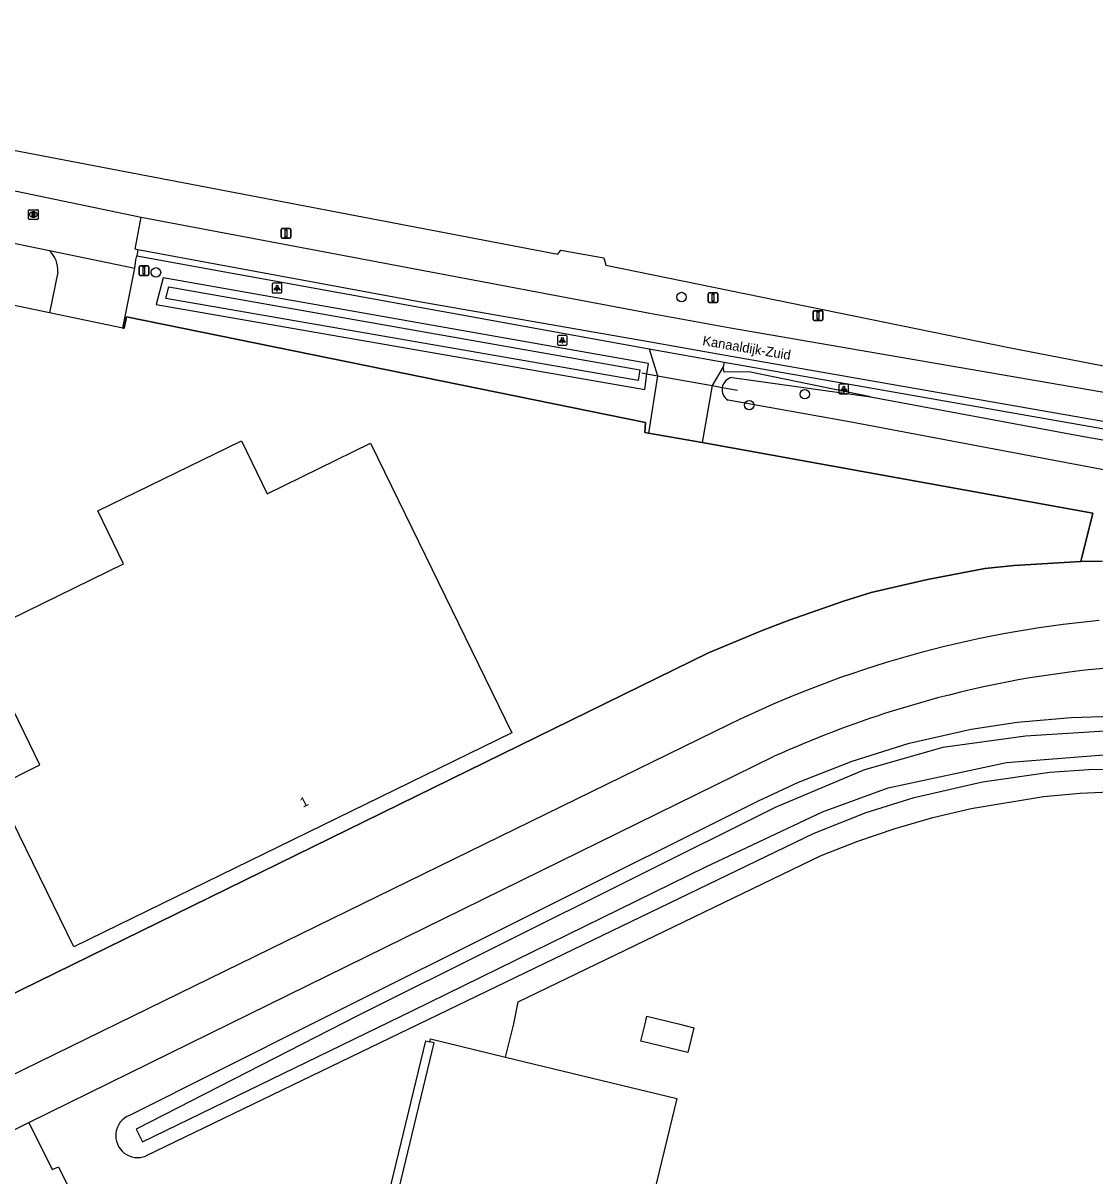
# Model space of a CAD drawing. Extents: x 163046 to 165074, y 382019 to 382874.
# Drawn here: x 163250 to 163360.8, y 382734.3 to 382853.5 of the extents above; entities that cross this region are included whole.
import ezdxf

# ---------------------------------------------------------------- set-up
doc = ezdxf.new("R2010")
doc.units = 0
for name, color, linetype in [('IMGEO_Afsluitpaal', 7, 'Continuous'), ('IMGEO_Boom', 7, 'Continuous'), ('IMGEO_Duiker', 7, 'Continuous'), ('IMGEO_Fietspad_gesloten', 7, 'Continuous'), ('IMGEO_Groenvoorziening', 7, 'Continuous'), ('IMGEO_Hek', 7, 'Continuous'), ('IMGEO_Lichtpunt', 7, 'Continuous'), ('IMGEO_Openbare_ruimte_label', 7, 'Continuous'), ('IMGEO_Pand', 7, 'Continuous'), ('IMGEO_Pand_nummerreeks', 7, 'Continuous'), ('IMGEO_Rijbaan_lokaal_gesloten', 7, 'Continuous'), ('IMGEO_Rijbaan_lokaal_halfverhard', 7, 'Continuous'), ('IMGEO_Rijbaan_lokaal_open', 7, 'Continuous'), ('IMGEO_Rioolput', 7, 'Continuous'), ('IMGEO_Verkeersbordpaal', 7, 'Continuous'), ('IMGEO_Voetpad_open', 7, 'Continuous'), ('IMGEO_Waterloop', 7, 'Continuous')]:
    doc.layers.add(name, color=color, linetype=linetype)

msp = doc.modelspace()

# ---------------------------------------------------------------- linework, layer by layer
at = {"layer": 'IMGEO_Afsluitpaal'}
for p, q in [((163320.83, 382824.69), (163320.83, 382825.49)), ((163320.83, 382825.49), (163320.83, 382824.69)), ((163320.93, 382825.59), (163321.72, 382825.59)), ((163321.72, 382825.59), (163320.93, 382825.59)), ((163321.82, 382825.49), (163321.82, 382824.69)), ((163321.82, 382824.69), (163321.82, 382825.49)), ((163321.72, 382824.59), (163320.93, 382824.59)), ((163320.93, 382824.59), (163321.72, 382824.59)), ((163331.68, 382822.85), (163331.68, 382823.65)), ((163331.68, 382823.65), (163331.68, 382822.85)), ((163331.78, 382823.75), (163332.57, 382823.75)), ((163332.57, 382823.75), (163331.78, 382823.75)), ((163332.67, 382823.65), (163332.67, 382822.85)), ((163332.67, 382822.85), (163332.67, 382823.65)), ((163332.57, 382822.75), (163331.78, 382822.75)), ((163331.78, 382822.75), (163332.57, 382822.75))]:
    msp.add_line(p, q, dxfattribs=at)
for points in [[(163321.25, 382825.47), (163321.4, 382825.47), (163321.4, 382824.72), (163321.25, 382824.72), (163321.25, 382825.47)], [(163332.1, 382823.62), (163332.25, 382823.62), (163332.25, 382822.87), (163332.1, 382822.87), (163332.1, 382823.62)]]:
    msp.add_lwpolyline(points, dxfattribs=at)
for centre, start, end in [((163320.93, 382825.49), 90, 180), ((163320.93, 382825.49), 90, 180), ((163321.72, 382825.49), 0, 90), ((163321.72, 382825.49), 360, 90), ((163320.93, 382824.69), 180, 270), ((163320.93, 382824.69), 180, 270), ((163321.72, 382824.69), 270, 0), ((163321.72, 382824.69), 270, 0), ((163331.78, 382823.65), 90, 180), ((163331.78, 382823.65), 90, 180), ((163332.57, 382823.65), 0, 90), ((163332.57, 382823.65), 360, 90), ((163331.78, 382822.85), 180, 270), ((163331.78, 382822.85), 180, 270), ((163332.57, 382822.85), 270, 0), ((163332.57, 382822.85), 270, 0)]:
    msp.add_arc(centre, 0.1, start, end, dxfattribs=at)
at = {"layer": 'IMGEO_Boom'}
for centre in [(163263.72, 382827.71), (163318.07, 382825.16), (163330.81, 382815.11), (163325.07, 382813.99)]:
    msp.add_circle(centre, 0.489, dxfattribs=at)
at = {"layer": 'IMGEO_Duiker'}
msp.add_lwpolyline([(163313.96, 382817.31), (163314.48, 382817.22), (163315.59, 382817.02), (163321.22, 382816), (163322.27, 382815.81), (163323.84, 382815.53)], dxfattribs=at)
at = {"layer": 'IMGEO_Fietspad_gesloten'}
msp.add_lwpolyline([(163262.2, 382833.43), (163314.79, 382823.48), (163323.12, 382821.97), (163364.34, 382814.88), (163364.32, 382814.73), (163391.13, 382810.02), (163404.12, 382807.82), (163422.79, 382804.65), (163452.38, 382800.08), (163452.39, 382800.23), (163481.75, 382795.75), (163600.16, 382778.49), (163659.31, 382769.79), (163694.75, 382764.5), (163718.27, 382760.99), (163718.28, 382761.09), (163777.46, 382752.55), (163894.24, 382735.48), (163935.71, 382729.35)], dxfattribs=at)
at = {"layer": 'IMGEO_Groenvoorziening'}
for points in [[(163252.7, 382823.52), (163242.43, 382825.65), (163242.33, 382825.25), (163240, 382825.68), (163241.32, 382832.3)], [(163264.46, 382827.14), (163263.75, 382824.38), (163314.26, 382815.6), (163314.48, 382817.22), (163314.64, 382818.3), (163264.46, 382827.14)], [(163314.65, 382811.1), (163314.26, 382811.17), (163314.35, 382812.18), (163260.67, 382823.11), (163260.43, 382821.93), (163260.28, 382821.96)], [(163337.61, 382814.84), (163325.03, 382817.42), (163322.49, 382817.39), (163322.36, 382817.94)], [(163359.37, 382797.83), (163360.61, 382802.83), (163320.19, 382810.11)], [(163200.21, 382729.51), (163222.08, 382740.26), (163242.58, 382750), (163320.84, 382788.38), (163326.4, 382790.68), (163329.21, 382791.76), (163334.82, 382793.72), (163337.67, 382794.6), (163343.5, 382795.94), (163349.43, 382797.09), (163352.45, 382797.4), (163359.37, 382797.83)], [(163359.37, 382797.83), (163374.85, 382798.03), (163401.89, 382794.15), (163410.94, 382792.85), (163500, 382779.47), (163535.41, 382774.6), (163550.62, 382772.33), (163693.06, 382751.36), (163828.8, 382731.36), (163846.1, 382728.88), (163873.33, 382724.84), (163916.5, 382718.52), (163943.51, 382714.37), (163981.6, 382708.67), (164080.42, 382694.02), (164103.91, 382690.52), (164197.42, 382676.27), (164217.65, 382673.07), (164282.56, 382663.33), (164518.36, 382627.93)], [(163410.61, 382775.99), (163377.55, 382781.04), (163372.54, 382781.55), (163367.86, 382781.78), (163363.62, 382781.82), (163358.36, 382781.66), (163352.77, 382781.17), (163348.02, 382780.45), (163341.46, 382778.95), (163335.66, 382777.14), (163330.14, 382774.97), (163325.99, 382773.04), (163279.88, 382750), (163260.97, 382740.55)], [(163290.93, 382750), (163331.78, 382769.74), (163337.15, 382771.86), (163342.11, 382773.43), (163349.17, 382775.05), (163356.16, 382776.02), (163360.19, 382776.32), (163367.6, 382776.42), (163374.36, 382776.08), (163380.14, 382775.41), (163410.26, 382770.79)], [(163299.86, 382746.58), (163300.71, 382750), (163301.17, 382752.29), (163332.52, 382767.41), (163336.3, 382768.91), (163340.15, 382770.21), (163344.05, 382771.34), (163348.01, 382772.28), (163355.5, 382773.52), (163359.28, 382773.88), (163363.07, 382774.05), (163367.27, 382774.02), (163371.45, 382773.73), (163379.79, 382772.82), (163396.27, 382770.52), (163405.32, 382768.66), (163412.39, 382767.2)], [(163262.68, 382736.35), (163290.93, 382750)], [(163250.57, 382739.8), (163252.99, 382734.96), (163253.66, 382735.24), (163267.35, 382707.42), (163272.62, 382706.27)]]:
    msp.add_lwpolyline(points, dxfattribs=at)
msp.add_arc((163261.83, 382738.45), 2.27, 112.1789, 292.2118, dxfattribs=at)
at = {"layer": 'IMGEO_Hek'}
for points in [[(163260.28, 382821.96), (163260.43, 382821.93), (163260.67, 382823.11), (163314.35, 382812.18), (163314.26, 382811.17), (163314.65, 382811.1)], [(163314.65, 382811.1), (163320.19, 382810.11)], [(163320.19, 382810.11), (163360.61, 382802.83), (163359.37, 382797.83)], [(163359.37, 382797.83), (163352.45, 382797.4), (163349.43, 382797.09), (163343.5, 382795.94), (163337.67, 382794.6), (163334.82, 382793.72), (163329.21, 382791.76), (163326.4, 382790.68), (163320.84, 382788.38), (163242.58, 382750), (163222.08, 382740.26)], [(163401.89, 382794.15), (163374.85, 382798.03), (163359.37, 382797.83)]]:
    msp.add_lwpolyline(points, dxfattribs=at)
at = {"layer": 'IMGEO_Lichtpunt'}
for p, q in [((163275.75, 382826.49), (163275.75, 382825.68)), ((163275.75, 382826.49), (163275.75, 382825.68)), ((163276.65, 382826.58), (163275.84, 382826.58)), ((163276.65, 382826.58), (163275.84, 382826.58)), ((163276.74, 382825.68), (163276.74, 382826.49)), ((163276.74, 382825.68), (163276.74, 382826.49)), ((163275.84, 382825.58), (163276.65, 382825.58)), ((163275.84, 382825.58), (163276.65, 382825.58)), ((163306.14, 382821.18), (163305.34, 382821.18)), ((163306.14, 382821.18), (163305.34, 382821.18)), ((163305.24, 382821.09), (163305.24, 382820.28)), ((163305.24, 382821.09), (163305.24, 382820.28)), ((163305.34, 382820.18), (163306.14, 382820.18)), ((163305.34, 382820.18), (163306.14, 382820.18)), ((163306.24, 382820.28), (163306.24, 382821.09)), ((163306.24, 382820.28), (163306.24, 382821.09)), ((163334.34, 382816.05), (163334.34, 382815.24)), ((163334.34, 382816.05), (163334.34, 382815.24)), ((163335.25, 382816.14), (163334.44, 382816.14)), ((163335.25, 382816.14), (163334.44, 382816.14)), ((163335.34, 382815.24), (163335.34, 382816.05)), ((163335.34, 382815.24), (163335.34, 382816.05)), ((163334.44, 382815.14), (163335.25, 382815.14)), ((163334.44, 382815.14), (163335.25, 382815.14))]:
    msp.add_line(p, q, dxfattribs=at)
for points in [[(163276.12, 382826.15), (163276.16, 382826.12), (163275.97, 382825.86), (163275.93, 382825.89), (163276.12, 382826.15)], [(163276.22, 382826.1), (163276.27, 382826.1), (163276.27, 382825.78), (163276.22, 382825.78), (163276.22, 382826.1)], [(163276.33, 382826.12), (163276.37, 382826.15), (163276.56, 382825.89), (163276.52, 382825.86), (163276.33, 382826.12)], [(163305.62, 382820.75), (163305.65, 382820.72), (163305.47, 382820.46), (163305.43, 382820.49), (163305.62, 382820.75)], [(163305.72, 382820.7), (163305.76, 382820.7), (163305.76, 382820.38), (163305.72, 382820.38), (163305.72, 382820.7)], [(163305.83, 382820.72), (163305.87, 382820.75), (163306.05, 382820.49), (163306.01, 382820.46), (163305.83, 382820.72)], [(163334.72, 382815.71), (163334.76, 382815.68), (163334.57, 382815.42), (163334.53, 382815.45), (163334.72, 382815.71)], [(163334.82, 382815.66), (163334.87, 382815.66), (163334.87, 382815.34), (163334.82, 382815.34), (163334.82, 382815.66)], [(163334.93, 382815.68), (163334.97, 382815.71), (163335.15, 382815.45), (163335.12, 382815.42), (163334.93, 382815.68)]]:
    msp.add_lwpolyline(points, dxfattribs=at)
for centre in [(163276.25, 382826.28), (163305.74, 382820.88), (163334.84, 382815.84)]:
    msp.add_circle(centre, 0.0994, dxfattribs=at)
for centre, start, end in [((163275.84, 382826.49), 90, 180), ((163275.84, 382826.49), 90, 180), ((163276.65, 382826.49), 0, 90), ((163276.65, 382826.49), 0, 90), ((163275.84, 382825.68), 180, 270), ((163275.84, 382825.68), 180, 270), ((163276.65, 382825.68), 270, 0), ((163276.65, 382825.68), 270, 360), ((163305.34, 382821.09), 90, 180), ((163305.34, 382821.09), 90, 180), ((163306.14, 382821.09), 0, 90), ((163306.14, 382821.09), 0, 90), ((163305.34, 382820.28), 180, 270), ((163305.34, 382820.28), 180, 270), ((163306.14, 382820.28), 270, 0), ((163306.14, 382820.28), 270, 360), ((163334.44, 382816.05), 90, 180), ((163334.44, 382816.05), 90, 180), ((163334.44, 382815.24), 180, 270), ((163334.44, 382815.24), 180, 270), ((163335.25, 382816.05), 0, 90), ((163335.25, 382816.05), 0, 90), ((163335.25, 382815.24), 270, 0), ((163335.25, 382815.24), 270, 360)]:
    msp.add_arc(centre, 0.0946, start, end, dxfattribs=at)
at = {"layer": 'IMGEO_Pand'}
for points in [[(163260.37, 382797.58), (163257.72, 382803.04), (163272.56, 382810.28), (163275.22, 382804.81), (163285.92, 382810.05), (163288.8, 382804.14), (163299.84, 382781.52), (163300.53, 382780.1), (163259.8, 382760.22), (163255.22, 382757.98), (163249.59, 382769.57), (163247.16, 382774.53), (163251.73, 382776.78), (163245.19, 382790.17), (163260.37, 382797.58)], [(163318.73, 382747.05), (163313.87, 382748.23), (163314.3, 382750), (163314.49, 382750.79), (163317.75, 382750), (163319.35, 382749.61), (163318.73, 382747.05)], [(163292.04, 382748.16), (163292.1, 382748.46), (163299.86, 382746.58)], [(163272.52, 382702.03), (163274.6, 382710.58), (163282.98, 382708.54), (163292.5, 382748.05), (163292.04, 382748.16)], [(163299.86, 382746.58), (163317.58, 382742.29), (163309.71, 382709.84), (163307.96, 382710.26), (163303.52, 382691.87), (163306.7, 382691.1), (163308.24, 382697.44), (163336.81, 382690.5), (163330.78, 382665.69)]]:
    msp.add_lwpolyline(points, dxfattribs=at)
at = {"layer": 'IMGEO_Rijbaan_lokaal_gesloten'}
for points in [[(163323, 382780.97), (163259.7, 382750), (163248.36, 382744.45)], [(163250.57, 382739.8), (163271.32, 382750), (163327.66, 382777.68)], [(163245.68, 382737.41), (163250.57, 382739.8)]]:
    msp.add_lwpolyline(points, dxfattribs=at)
for centre, radius, start, end in [((163371.42, 382682.09), 110.09, 95.3015, 116.0933), ((163371.32, 382683.11), 104.1, 86.0718, 107.6052), ((163374.62, 382673.1), 114.64, 107.6645, 114.1814)]:
    msp.add_arc(centre, radius, start, end, dxfattribs=at)
at = {"layer": 'IMGEO_Rijbaan_lokaal_halfverhard'}
for points in [[(163935.2, 382726.45), (163865.22, 382736.76), (163777.02, 382749.58), (163717.86, 382758.17), (163694.37, 382761.68), (163658.89, 382766.97), (163481.33, 382792.88), (163422.35, 382801.94), (163403.68, 382805.1), (163390.65, 382807.22), (163363.84, 382811.92), (163322.62, 382819.12), (163314.27, 382820.6), (163290.92, 382824.68), (163261.84, 382830.05)], [(163261.73, 382829.42), (163314.71, 382819.8)], [(163314.71, 382819.8), (163322.47, 382818.43)], [(163322.47, 382818.43), (163367.47, 382810.55), (163392.06, 382806.33), (163416.38, 382802.09), (163437.86, 382798.77), (163477.86, 382792.74), (163535.08, 382784.39), (163586.49, 382776.8), (163665.19, 382765.27), (163724.04, 382756.55), (163797.09, 382745.94), (163942.52, 382724.63), (163982.95, 382718.82), (164038.68, 382710.5), (164106.21, 382700.45), (164167.93, 382691.09), (164227.93, 382681.9), (164243.96, 382679.59)]]:
    msp.add_lwpolyline(points, dxfattribs=at)
at = {"layer": 'IMGEO_Rijbaan_lokaal_open'}
for points in [[(163170.92, 382852.45), (163262.2, 382833.43)], [(163261.84, 382830.05), (163261.58, 382830.1), (163262.2, 382833.43)], [(163241.32, 382832.3), (163252.7, 382829.96)], [(163252.7, 382829.96), (163261.55, 382828.14)], [(163261.84, 382830.05), (163261.73, 382829.42)], [(163261.55, 382828.14), (163261.65, 382829.02), (163261.73, 382829.42)]]:
    msp.add_lwpolyline(points, dxfattribs=at)
at = {"layer": 'IMGEO_Rioolput'}
for p, q in [((163250.54, 382833.26), (163250.54, 382834.11)), ((163250.62, 382834.19), (163251.47, 382834.19)), ((163251.47, 382833.19), (163250.62, 382833.19)), ((163251.03, 382833.97), (163251.06, 382833.97)), ((163251.05, 382833.41), (163251.03, 382833.41)), ((163251.54, 382834.11), (163251.54, 382833.26))]:
    msp.add_line(p, q, dxfattribs=at)
for points in [[(163250.54, 382833.26), (163250.54, 382834.11)], [(163250.62, 382834.19), (163251.47, 382834.19)], [(163251.47, 382833.19), (163250.62, 382833.19)], [(163251.13, 382833.88), (163250.88, 382833.89), (163250.88, 382833.49)], [(163250.88, 382833.49), (163251, 382833.49), (163251, 382833.65), (163251.02, 382833.65)], [(163251.06, 382833.81), (163251, 382833.81), (163251, 382833.72)], [(163251, 382833.72), (163251.06, 382833.72)], [(163251.06, 382833.62), (163251.13, 382833.49), (163251.27, 382833.49), (163251.21, 382833.61)], [(163251.54, 382834.11), (163251.54, 382833.26)]]:
    msp.add_lwpolyline(points, dxfattribs=at)
for centre, radius, start, end in [((163250.62, 382834.11), 0.0765, 91.552, 178.448), ((163250.62, 382834.11), 0.0765, 91.552, 178.448), ((163250.62, 382833.26), 0.0765, 181.552, 268.448), ((163250.62, 382833.26), 0.0765, 181.552, 268.448), ((163251.01, 382833.6), 0.0533, 26.0293, 88.6989), ((163251.06, 382833.71), 0.0964, 77.0061, 93.1865), ((163251.04, 382833.91), 0.19, 274.7715, 282.9687), ((163251.08, 382833.77), 0.0378, 276.6634, 79.6772), ((163251.13, 382833.77), 0.109, 350.3612, 89.416), ((163251.13, 382833.77), 0.112, 277.5842, 350.9817), ((163251.11, 382833.56), 0.108, 29.5134, 73.7905), ((163251.47, 382834.11), 0.0765, 1.552, 88.448), ((163251.47, 382834.11), 0.0765, 1.552, 88.448), ((163251.47, 382833.26), 0.0765, 271.552, 358.448), ((163251.47, 382833.26), 0.0765, 271.552, 358.448)]:
    msp.add_arc(centre, radius, start, end, dxfattribs=at)
for centre, major_axis, ratio, start_param, end_param in [((163251.03, 382833.69), (-0.387, 0.002), 0.722429, 4.712389, 7.853982), ((163251.05, 382833.69), (-0.39, 0.002), 0.717154, 1.570796, 4.712389)]:
    msp.add_ellipse(centre, major_axis=major_axis, ratio=ratio, start_param=start_param, end_param=end_param, dxfattribs=at)
at = {"layer": 'IMGEO_Verkeersbordpaal'}
for p, q in [((163276.67, 382831.34), (163276.67, 382832.14)), ((163276.67, 382832.14), (163276.67, 382831.34)), ((163276.77, 382832.24), (163277.56, 382832.24)), ((163277.56, 382832.24), (163276.77, 382832.24)), ((163277.66, 382832.14), (163277.66, 382831.34)), ((163277.66, 382831.34), (163277.66, 382832.14)), ((163277.56, 382831.24), (163276.77, 382831.24)), ((163276.77, 382831.24), (163277.56, 382831.24)), ((163261.98, 382827.5), (163261.98, 382828.3)), ((163261.98, 382828.3), (163261.98, 382827.5)), ((163262.08, 382828.4), (163262.87, 382828.4)), ((163262.87, 382828.4), (163262.08, 382828.4)), ((163262.97, 382828.3), (163262.97, 382827.5)), ((163262.97, 382827.5), (163262.97, 382828.3)), ((163262.87, 382827.4), (163262.08, 382827.4)), ((163262.08, 382827.4), (163262.87, 382827.4))]:
    msp.add_line(p, q, dxfattribs=at)
for points in [[(163277.09, 382832.11), (163277.24, 382832.11), (163277.24, 382831.36), (163277.09, 382831.36), (163277.09, 382832.11)], [(163262.4, 382828.27), (163262.55, 382828.27), (163262.55, 382827.52), (163262.4, 382827.52), (163262.4, 382828.27)]]:
    msp.add_lwpolyline(points, dxfattribs=at)
for centre, start, end in [((163276.77, 382832.14), 90, 180), ((163276.77, 382832.14), 90, 180), ((163277.56, 382832.14), 0, 90), ((163277.56, 382832.14), 360, 90), ((163276.77, 382831.34), 180, 270), ((163276.77, 382831.34), 180, 270), ((163277.56, 382831.34), 270, 0), ((163277.56, 382831.34), 270, 0), ((163262.08, 382828.3), 90, 180), ((163262.08, 382828.3), 90, 180), ((163262.87, 382828.3), 0, 90), ((163262.87, 382828.3), 360, 90), ((163262.08, 382827.5), 180, 270), ((163262.08, 382827.5), 180, 270), ((163262.87, 382827.5), 270, 0), ((163262.87, 382827.5), 270, 0)]:
    msp.add_arc(centre, 0.1, start, end, dxfattribs=at)
at = {"layer": 'IMGEO_Voetpad_open'}
for points in [[(163253.56, 382827.74), (163252.7, 382823.52)], [(163260.28, 382821.96), (163261.55, 382828.14)], [(163260.28, 382821.96), (163252.7, 382823.52)], [(163314.71, 382819.8), (163315.59, 382817.02), (163314.65, 382811.1)], [(163322.36, 382817.94), (163321.22, 382816), (163320.19, 382810.11)], [(163322.47, 382818.43), (163322.36, 382817.94)], [(163320.19, 382810.11), (163314.65, 382811.1)], [(163272.62, 382706.27), (163273.94, 382711.66), (163282.29, 382709.63), (163291.64, 382748.27), (163292.04, 382748.16)]]:
    msp.add_lwpolyline(points, dxfattribs=at)
msp.add_arc((163250.9, 382827.98), 2.67, 354.7682, 47.6731, dxfattribs=at)
at = {"layer": 'IMGEO_Waterloop'}
for points in [[(163181.62, 382853.49), (163197.03, 382850.28), (163305.26, 382829.6), (163305.57, 382830.01), (163310.04, 382829.2), (163310.24, 382828.46), (163351.91, 382819.96), (163378.29, 382814.85), (163404.52, 382810.31), (163423.67, 382806.99), (163441.72, 382804), (163484.72, 382798.05), (163500, 382795.74), (163550.36, 382788.13), (163695.04, 382766.67), (163750, 382758.53), (163787.83, 382753.17), (163808.82, 382750), (163842.64, 382744.9), (163893.44, 382737.78), (163957.08, 382728.48), (163984.26, 382724.67)], [(163313.58, 382816.53), (163264.74, 382825.02), (163265.05, 382826.23), (163313.74, 382817.65), (163313.58, 382816.53)], [(163323.3, 382816.84), (163337.61, 382814.84)], [(163960.72, 382718.96), (163901.57, 382725.6), (163891.58, 382726.84), (163814.14, 382738.31), (163792.78, 382741.61), (163745.19, 382750), (163693.63, 382755.7), (163644.4, 382763.31), (163599.03, 382769.82), (163550.48, 382777.74), (163531.31, 382780.73), (163500, 382785.31), (163403.56, 382799.39), (163402.77, 382799.54), (163335.61, 382812.21), (163322.88, 382814.5)], [(163337.61, 382814.84), (163359.3, 382810.82), (163403.34, 382803.03), (163422.96, 382799.57), (163500, 382787.56), (163548.66, 382779.98), (163558.31, 382778.65), (163599.59, 382773.47), (163692, 382760.32), (163694.14, 382759.99), (163759.96, 382750), (163780.57, 382747.06), (163793.38, 382745.36), (163843.66, 382737.95), (163892.47, 382731.14), (163941.47, 382723.93), (163961.29, 382721.23)], [(163261.69, 382739.13), (163262.33, 382737.81), (163290.23, 382751.36), (163320.59, 382766.26), (163332.65, 382771.95), (163339.44, 382774.41), (163351.67, 382777.05), (163364.75, 382778.07), (163384.88, 382776.2), (163410.31, 382772.38), (163410.57, 382774.16), (163392.9, 382777.13), (163373.83, 382779.72), (163368.23, 382780.25), (163364.71, 382780.36), (163361.84, 382780.27), (163353.64, 382779.76), (163345.07, 382778.57), (163337, 382776.28), (163327.74, 382772.38), (163284.56, 382750.85), (163261.69, 382739.13)]]:
    msp.add_lwpolyline(points, dxfattribs=at)
for start, end in [(100.1063, 170.0054), (169.9597, 239.7064)]:
    msp.add_arc((163323.52, 382815.59), 1.27, start, end, dxfattribs=at)

# ---------------------------------------------------------------- texts
at = {"layer": 'IMGEO_Openbare_ruimte_label'}
msp.add_text('Kanaaldijk-Zuid', height=1, rotation=350.387, dxfattribs=at).set_placement((163320.18, 382820.19))
at = {"layer": 'IMGEO_Pand_nummerreeks'}
msp.add_text('1', height=1, rotation=26.0189, dxfattribs=at).set_placement((163278.92, 382772.35))

doc.saveas('drawing.dxf')
